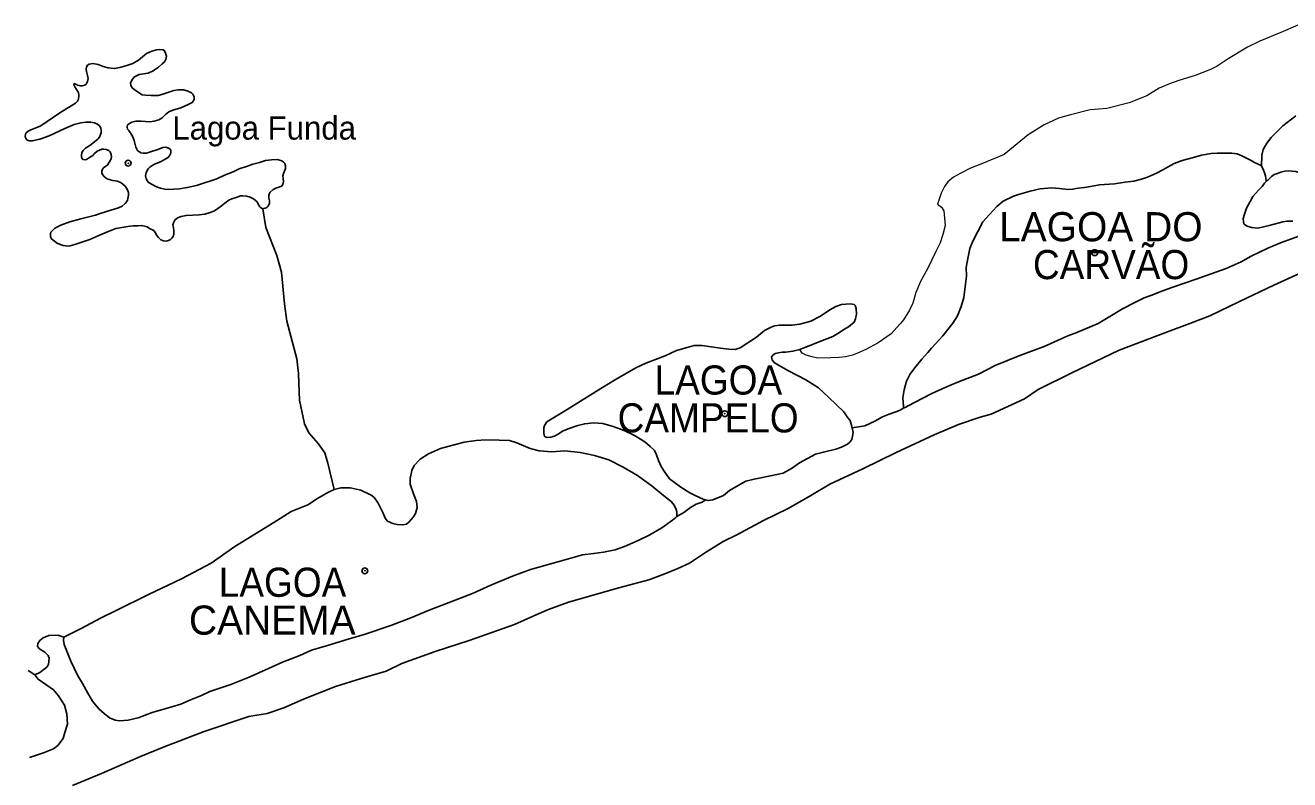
# Model space of a CAD drawing. Extents: x 267.7 to 296, y 7537.7 to 7565.8.
# Drawn here: x 267.927 to 272.267, y 7548.999 to 7551.589 of the extents above; entities that cross this region are included whole.
import ezdxf
from ezdxf.enums import TextEntityAlignment as Align

# ---------------------------------------------------------------- set-up
doc = ezdxf.new("R2010")
doc.units = 0
doc.header["$LTSCALE"] = 0.04
doc.header["$PDMODE"] = 32
doc.header["$PDSIZE"] = 0.02
doc.linetypes.add('SHORT_DASHED', pattern=[2.7, 1.5, -1.2])
for name, color, linetype, lineweight in [('2', 7, 'Continuous', 25), ('21', 7, 'SHORT_DASHED', 13), ('7', 7, 'Continuous', 25)]:
    doc.layers.add(name, color=color, linetype=linetype, lineweight=lineweight)
doc.layers.add('61', color=7, linetype='Continuous')

msp = doc.modelspace()

# ---------------------------------------------------------------- linework, layer by layer
at = {"layer": '2'}
for points in [[(268.1366, 7551.4305), (268.1361, 7551.4383), (268.1366, 7551.4472), (268.1408, 7551.4524), (268.146, 7551.4556), (268.1591, 7551.4582), (268.1768, 7551.455), (268.1946, 7551.4482), (268.2113, 7551.4435), (268.2322, 7551.4409), (268.251, 7551.4446), (268.275, 7551.4514), (268.2965, 7551.4587), (268.3153, 7551.4691), (268.3288, 7551.4806), (268.3435, 7551.4926), (268.3617, 7551.501), (268.3774, 7551.5047), (268.3884, 7551.5062), (268.3999, 7551.5052), (268.4051, 7551.502), (268.4087, 7551.4937), (268.4114, 7551.4832), (268.4093, 7551.4723), (268.4035, 7551.4629), (268.3967, 7551.4576), (268.3837, 7551.4456), (268.3659, 7551.4336), (268.3487, 7551.4253), (268.3179, 7551.4206), (268.3017, 7551.4127), (268.2954, 7551.4049), (268.2886, 7551.3924), (268.2891, 7551.3824), (268.2954, 7551.373), (268.3116, 7551.3605), (268.3278, 7551.3506), (268.3393, 7551.3495), (268.3591, 7551.3485), (268.3826, 7551.348), (268.3952, 7551.3516), (268.437, 7551.3657), (268.4516, 7551.3683), (268.4704, 7551.3683), (268.4829, 7551.3642), (268.497, 7551.3579), (268.5022, 7551.3527), (268.5064, 7551.3433), (268.5064, 7551.3349), (268.5012, 7551.3255), (268.4996, 7551.3245), (268.4855, 7551.3177), (268.461, 7551.3062), (268.4328, 7551.2983), (268.4197, 7551.2926), (268.4082, 7551.2832), (268.3962, 7551.2712), (268.3852, 7551.2644), (268.3691, 7551.2607), (268.3544, 7551.2581), (268.3247, 7551.2597), (268.3059, 7551.2597), (268.2923, 7551.2566), (268.2844, 7551.2524), (268.2776, 7551.2472), (268.2761, 7551.2398), (268.2776, 7551.2331), (268.2818, 7551.2278), (268.2949, 7551.2085), (268.3001, 7551.1939), (268.3059, 7551.1714), (268.3116, 7551.1594), (268.3236, 7551.1521), (268.3325, 7551.15), (268.3435, 7551.1505), (268.3602, 7551.1558), (268.3753, 7551.1605), (268.3905, 7551.1662), (268.3993, 7551.1699), (268.4098, 7551.1709), (268.4187, 7551.1672), (268.4239, 7551.1636), (268.426, 7551.1594), (268.426, 7551.15), (268.4234, 7551.1437), (268.4171, 7551.1354), (268.4072, 7551.1296), (268.391, 7551.1208), (268.3701, 7551.1124), (268.355, 7551.1035), (268.3482, 7551.0967), (268.3419, 7551.0837), (268.3398, 7551.0727), (268.3419, 7551.0617), (268.3487, 7551.0508)], [(268.1366, 7551.4305), (268.1402, 7551.4174), (268.1425, 7551.4064), (268.1405, 7551.3969), (268.1354, 7551.3871), (268.1311, 7551.3844), (268.1225, 7551.3812), (268.1174, 7551.3816), (268.1154, 7551.3816), (268.1115, 7551.3824), (268.1064, 7551.3844), (268.0981, 7551.3883), (268.0958, 7551.3895), (268.0942, 7551.3879), (268.0934, 7551.3852), (268.0954, 7551.3808), (268.0969, 7551.3781), (268.1028, 7551.3691), (268.1095, 7551.3588), (268.1107, 7551.3482), (268.1099, 7551.3353), (268.1064, 7551.3286), (268.0989, 7551.3223), (268.0451, 7551.2889), (267.9803, 7551.2438), (267.961, 7551.2367), (267.9461, 7551.2304), (267.9363, 7551.2257), (267.93, 7551.2206), (267.9277, 7551.2151), (267.9269, 7551.2076), (267.9304, 7551.1982), (267.932, 7551.1962), (267.9363, 7551.1939), (267.9422, 7551.1927), (267.9508, 7551.1923), (267.9764, 7551.1982), (268.009, 7551.2104), (268.0632, 7551.2351), (268.0946, 7551.2489), (268.1174, 7551.2544), (268.1347, 7551.2567), (268.1508, 7551.2571), (268.1645, 7551.2544), (268.1751, 7551.2504), (268.1818, 7551.2442), (268.1857, 7551.2367), (268.1869, 7551.2292), (268.1873, 7551.2206), (268.1849, 7551.2139), (268.1814, 7551.2049), (268.1755, 7551.199), (268.1488, 7551.1762), (268.1339, 7551.1672), (268.1256, 7551.1597), (268.1213, 7551.1526), (268.1193, 7551.1444), (268.1193, 7551.1373), (268.1217, 7551.1314), (268.1256, 7551.1291), (268.1327, 7551.1275), (268.1374, 7551.1287), (268.1476, 7551.135), (268.1582, 7551.1428), (268.1645, 7551.1491), (268.1731, 7551.1573), (268.1814, 7551.1609), (268.19, 7551.164), (268.1967, 7551.1644), (268.2042, 7551.1632), (268.2136, 7551.1593), (268.2179, 7551.1546), (268.2222, 7551.146), (268.2226, 7551.1381), (268.2215, 7551.1318), (268.2183, 7551.124), (268.2128, 7551.1157), (268.2097, 7551.1106), (268.2034, 7551.1059), (268.1955, 7551.0996), (268.1916, 7551.0949), (268.1896, 7551.0878), (268.1893, 7551.0823), (268.1916, 7551.0768), (268.1971, 7551.0698), (268.2054, 7551.0639), (268.2116, 7551.0615), (268.2277, 7551.056), (268.2431, 7551.054), (268.2537, 7551.0501), (268.2603, 7551.0454), (268.2702, 7551.0368), (268.2765, 7551.0265), (268.2808, 7551.0155), (268.2808, 7551.0057)], [(272.1703, 7551.1058), (272.171, 7551.1438), (272.1758, 7551.1629), (272.1885, 7551.1851), (272.2039, 7551.2042), (272.2431, 7551.244), (272.2882, 7551.279)], [(268.4364, 7551.0267), (268.4558, 7551.0278), (268.4829, 7551.032), (268.5143, 7551.0398), (268.5848, 7551.0628), (268.6104, 7551.0748), (268.6401, 7551.0863), (268.6615, 7551.0967), (268.6898, 7551.1061), (268.7075, 7551.1124), (268.7305, 7551.1187), (268.7519, 7551.1249), (268.7718, 7551.127), (268.7921, 7551.1281), (268.8073, 7551.1239), (268.813, 7551.1197), (268.8177, 7551.115), (268.8203, 7551.1067), (268.8203, 7551.0973), (268.8135, 7551.0811), (268.8114, 7551.0727), (268.8125, 7551.0633), (268.8135, 7551.0529), (268.8109, 7551.0429), (268.8067, 7551.0372), (268.801, 7551.0351), (268.7869, 7551.0299), (268.7775, 7551.0257), (268.7665, 7551.0158), (268.7624, 7551.0064), (268.7629, 7550.9959), (268.765, 7550.987), (268.765, 7550.9782), (268.7603, 7550.9688), (268.7571, 7550.9646), (268.754, 7550.963), (268.7425, 7550.9595)], [(270.9429, 7550.2763), (270.9413, 7550.2783), (270.9409, 7550.2811), (270.9397, 7550.3101), (270.9432, 7550.3376), (270.952, 7550.3674), (270.9635, 7550.3909), (270.9791, 7550.4124), (271.0045, 7550.4435), (271.0248, 7550.4661), (271.038, 7550.4813), (271.0766, 7550.5235), (271.1108, 7550.5672), (271.1263, 7550.5915), (271.1391, 7550.6238), (271.1486, 7550.6544), (271.1574, 7550.728), (271.1566, 7550.7583), (271.1618, 7550.7885), (271.1689, 7550.8236), (271.1797, 7550.8482), (271.2135, 7550.9143), (271.2366, 7550.9394), (271.2621, 7550.9672), (271.284, 7550.986), (271.319, 7551.0023), (271.3357, 7551.0082), (271.3767, 7551.0194), (271.4101, 7551.0274), (271.4491, 7551.0309), (271.477, 7551.0293), (271.5057, 7551.0262), (271.5228, 7551.0266), (271.5331, 7551.0289), (271.5709, 7551.0341), (271.6139, 7551.0421), (271.6661, 7551.0449), (271.7027, 7551.0504), (271.7321, 7551.054), (271.7584, 7551.0612), (271.7791, 7551.0679), (271.8101, 7551.0819), (271.834, 7551.0942), (271.8503, 7551.1038), (271.8702, 7551.1153), (271.8985, 7551.1249), (271.9371, 7551.1356), (271.9646, 7551.1432), (271.9976, 7551.1487), (272.0183, 7551.1503), (272.0681, 7551.1503), (272.0864, 7551.1476), (272.1031, 7551.1408), (272.1353, 7551.1257), (272.1445, 7551.1193), (272.1592, 7551.1129), (272.1664, 7551.1089), (272.1703, 7551.1058)], [(272.1703, 7551.1058), (272.176, 7551.0958), (272.1801, 7551.083), (272.1838, 7551.0722), (272.1856, 7551.063), (272.1868, 7551.0562)], [(272.2503, 7551.0881), (272.237, 7551.0848), (272.2214, 7551.0798), (272.2142, 7551.0773), (272.2046, 7551.0702), (272.1974, 7551.0632), (272.1916, 7551.0572), (272.1898, 7551.0564), (272.1868, 7551.0562)], [(272.3077, 7551.079), (272.298, 7551.0843), (272.2884, 7551.0873), (272.2759, 7551.0891), (272.2633, 7551.0896), (272.2503, 7551.0881)], [(268.3487, 7551.0508), (268.3597, 7551.0445), (268.3774, 7551.0351), (268.3915, 7551.0304), (268.4108, 7551.0262), (268.4364, 7551.0267)], [(272.1868, 7551.0562), (272.1861, 7551.0527), (272.1811, 7551.0469), (272.1723, 7551.0365), (272.1596, 7551.0238), (272.1401, 7551.0015), (272.1309, 7550.984), (272.119, 7550.9613), (272.1106, 7550.9378), (272.1079, 7550.9255), (272.1083, 7550.9159), (272.1102, 7550.9079), (272.1154, 7550.9032), (272.121, 7550.9), (272.1361, 7550.8952), (272.158, 7550.8932), (272.1966, 7550.9016), (272.2304, 7550.9115), (272.244, 7550.9143), (272.2583, 7550.9171), (272.2774, 7550.9167)], [(268.2474, 7550.9629), (268.2211, 7550.9551), (268.1834, 7550.9437), (268.168, 7550.937), (268.1174, 7550.9248), (268.0793, 7550.9142), (268.0486, 7550.9032), (268.0353, 7550.8965), (268.0274, 7550.8914), (268.02, 7550.8851), (268.0149, 7550.8789), (268.0129, 7550.8738), (268.0129, 7550.8647), (268.0156, 7550.858), (268.0231, 7550.8514), (268.0361, 7550.8411), (268.0498, 7550.8357), (268.0569, 7550.8333), (268.073, 7550.8309), (268.0804, 7550.8317), (268.0973, 7550.8364), (268.1488, 7550.8541), (268.1794, 7550.8675), (268.2089, 7550.8804), (268.2372, 7550.8914), (268.2792, 7550.8989), (268.2977, 7550.9012), (268.3134, 7550.9009), (268.3248, 7550.9016), (268.3358, 7550.9001), (268.3448, 7550.8977), (268.353, 7550.8922), (268.368, 7550.8844), (268.3727, 7550.8781), (268.3786, 7550.8679), (268.3837, 7550.8608), (268.3884, 7550.8565), (268.3923, 7550.8529), (268.401, 7550.849), (268.41, 7550.8482), (268.4182, 7550.8502), (268.4257, 7550.8537), (268.4304, 7550.8584), (268.4344, 7550.8647), (268.4367, 7550.8726), (268.4363, 7550.8836), (268.4351, 7550.895), (268.4336, 7550.9048), (268.4355, 7550.9115), (268.4402, 7550.9209), (268.4497, 7550.928), (268.4622, 7550.9335), (268.4791, 7550.9366), (268.5235, 7550.939), (268.5432, 7550.9409), (268.562, 7550.9472), (268.5746, 7550.9511), (268.5832, 7550.957), (268.6009, 7550.97), (268.6123, 7550.979), (268.626, 7550.9888), (268.6359, 7550.9936), (268.6512, 7550.9983), (268.6661, 7551.0034), (268.6736, 7551.0038), (268.6877, 7551.003), (268.6987, 7550.9994), (268.7097, 7550.9939), (268.7168, 7550.9884), (268.7223, 7550.9829), (268.7262, 7550.9755), (268.7317, 7550.9664), (268.7356, 7550.9625), (268.7425, 7550.9595)], [(268.2808, 7551.0057), (268.2792, 7550.9943), (268.2772, 7550.9884), (268.2694, 7550.9774), (268.26, 7550.9688), (268.2474, 7550.9629)], [(272.2985, 7550.865), (272.2352, 7550.8431), (272.1922, 7550.824), (272.1353, 7550.7973), (272.1003, 7550.7774), (272.049, 7550.7539), (271.9459, 7550.7177), (271.8663, 7550.6906), (271.8245, 7550.6755), (271.7942, 7550.6632), (271.7679, 7550.6536), (271.7353, 7550.6377), (271.6935, 7550.6162), (271.6557, 7550.5935), (271.6091, 7550.566), (271.5367, 7550.5342), (271.5061, 7550.5231), (271.4241, 7550.4868), (271.3413, 7550.4562), (271.2561, 7550.4212), (271.1984, 7550.3921), (271.1307, 7550.3658), (271.0869, 7550.3471), (271.0384, 7550.3256), (271.0057, 7550.3081), (270.9572, 7550.2827), (270.9472, 7550.2775), (270.944, 7550.2763), (270.9429, 7550.2763)], [(272.3736, 7550.7707), (272.2126, 7550.6967), (272.0925, 7550.6398), (271.9927, 7550.5916), (271.924, 7550.5658), (271.8478, 7550.5369), (271.6816, 7550.4746), (271.5196, 7550.3963), (271.4037, 7550.3394), (271.3565, 7550.3073), (271.2996, 7550.2804), (271.2428, 7550.2547), (271.2041, 7550.244), (271.1301, 7550.2193), (271.0464, 7550.1839), (270.9166, 7550.1227), (270.8018, 7550.0669), (270.6881, 7550.0144), (270.6237, 7549.9757), (270.5454, 7549.9307), (270.4606, 7549.8888), (270.3694, 7549.8406), (270.3222, 7549.817), (270.2654, 7549.7816), (270.2064, 7549.7429), (270.1667, 7549.7247), (270.1227, 7549.7065), (270.0669, 7549.6861), (269.9639, 7549.6582), (269.7912, 7549.6088), (269.7225, 7549.5841), (269.6721, 7549.5616), (269.6056, 7549.5326), (269.4511, 7549.4779), (269.3341, 7549.4393), (269.2193, 7549.3985), (269.1657, 7549.3717), (269.1378, 7549.3642), (269.0798, 7549.347), (268.9919, 7549.3191), (268.8824, 7549.2762), (268.8149, 7549.2462), (268.7569, 7549.2269), (268.6947, 7549.2162), (268.5413, 7549.1647), (268.4039, 7549.1121), (268.3224, 7549.0788), (268.1883, 7549.0209), (268.0885, 7548.9801)], [(269.7182, 7550.1737), (269.712, 7550.1765), (269.7085, 7550.1806), (269.7065, 7550.1917), (269.7065, 7550.2069), (269.7092, 7550.2151), (269.7175, 7550.2275), (269.7865, 7550.2703), (269.9024, 7550.3427), (269.9548, 7550.3745), (270.0224, 7550.4138), (270.0569, 7550.429), (270.1231, 7550.4552), (270.1624, 7550.4731), (270.1983, 7550.4828), (270.2231, 7550.4897), (270.25, 7550.4897), (270.2818, 7550.4855), (270.3128, 7550.4814), (270.3418, 7550.4773), (270.3632, 7550.4759), (270.3804, 7550.4821), (270.437, 7550.5187), (270.4646, 7550.5414), (270.4867, 7550.5531), (270.4991, 7550.5573), (270.5163, 7550.5594), (270.5591, 7550.56), (270.5853, 7550.5635), (270.6025, 7550.5683), (270.6232, 7550.5738), (270.6543, 7550.5897), (270.6736, 7550.6028), (270.6888, 7550.6125), (270.7095, 7550.6235), (270.7281, 7550.6304), (270.7433, 7550.6325), (270.7591, 7550.6332), (270.7716, 7550.6311), (270.7757, 7550.627), (270.7785, 7550.6173), (270.7798, 7550.5973), (270.7764, 7550.5814), (270.7716, 7550.5704), (270.7529, 7550.5545), (270.7371, 7550.5449), (270.7219, 7550.5352), (270.6991, 7550.5214), (270.6577, 7550.5055), (270.6025, 7550.4835), (270.586, 7550.4766)], [(270.586, 7550.4766), (270.5618, 7550.4704), (270.5377, 7550.4669), (270.5253, 7550.4669), (270.5122, 7550.4655), (270.5011, 7550.4621), (270.4929, 7550.4566), (270.488, 7550.4497), (270.4908, 7550.4407), (270.4963, 7550.4331), (270.5046, 7550.4276), (270.5467, 7550.4035), (270.6067, 7550.3724), (270.6495, 7550.3448), (270.6853, 7550.3117), (270.7364, 7550.262), (270.7509, 7550.242), (270.7578, 7550.2331), (270.7619, 7550.2206), (270.7653, 7550.2069)], [(269.7182, 7550.1737), (269.7313, 7550.1751), (269.7437, 7550.1786), (269.7596, 7550.1875), (269.7706, 7550.1958), (269.7899, 7550.2041), (269.8237, 7550.2158), (269.8472, 7550.2213), (269.8775, 7550.2248), (269.9093, 7550.2227), (269.9444, 7550.2117), (269.9831, 7550.1986), (270.0176, 7550.1806), (270.0534, 7550.1593), (270.0714, 7550.1434), (270.0866, 7550.1296), (270.0941, 7550.1151), (270.101, 7550.0958), (270.11, 7550.0751), (270.1197, 7550.0585), (270.1383, 7550.0323), (270.1604, 7550.0158), (270.1776, 7550.004), (270.208, 7549.984), (270.2266, 7549.9751), (270.2535, 7549.9627), (270.2621, 7549.9602)], [(270.2621, 7549.9602), (270.2707, 7549.9578), (270.2866, 7549.9599), (270.3232, 7549.9751), (270.3439, 7549.9923), (270.3818, 7550.0137), (270.3997, 7550.024), (270.4287, 7550.0316), (270.4908, 7550.0434), (270.5287, 7550.0523), (270.557, 7550.0682), (270.5846, 7550.0875), (270.6115, 7550.102), (270.6398, 7550.1165), (270.6667, 7550.1241), (270.7095, 7550.1344), (270.7281, 7550.1406), (270.7495, 7550.151), (270.7571, 7550.1586), (270.764, 7550.1675), (270.7667, 7550.1786), (270.7681, 7550.1917), (270.7653, 7550.2069)], [(268.9866, 7549.9958), (269.0095, 7550.0014), (269.0424, 7550.0014), (269.0785, 7549.9934), (269.1162, 7549.9757), (269.1258, 7549.9669), (269.1386, 7549.9485), (269.1538, 7549.9164), (269.1619, 7549.8979), (269.1707, 7549.8875), (269.1883, 7549.8795), (269.2036, 7549.8755), (269.2228, 7549.8739), (269.2349, 7549.8771), (269.2437, 7549.8835), (269.2597, 7549.902), (269.2669, 7549.9132), (269.2725, 7549.934), (269.2701, 7549.9549), (269.2597, 7549.9814), (269.2485, 7550.0142), (269.2477, 7550.0335), (269.2541, 7550.0608), (269.2621, 7550.0784), (269.2822, 7550.1001), (269.311, 7550.1185), (269.3519, 7550.1361), (269.433, 7550.1578), (269.4747, 7550.1642), (269.5083, 7550.1666), (269.5541, 7550.165), (269.5885, 7550.1634), (269.6142, 7550.1554), (269.6599, 7550.1361), (269.6904, 7550.1281), (269.7345, 7550.1249), (269.7794, 7550.1289), (269.8316, 7550.1225), (269.8813, 7550.1129), (269.9302, 7550.0977), (269.9791, 7550.0728), (270.0281, 7550.0439), (270.0786, 7550.007), (270.105, 7549.9854), (270.1235, 7549.9709), (270.1435, 7549.9549), (270.154, 7549.9421), (270.1612, 7549.9268), (270.1636, 7549.9196), (270.1636, 7549.9036)], [(268.0591, 7549.4889), (268.116, 7549.517), (268.1874, 7549.5555), (268.2363, 7549.5795), (268.3502, 7549.6349), (268.4633, 7549.6894), (268.5644, 7549.7432), (268.6462, 7549.8001), (268.7897, 7549.8883), (268.8395, 7549.9204), (268.8964, 7549.9429), (268.9333, 7549.9677), (268.9678, 7549.987), (268.9866, 7549.9958)], [(268.0591, 7549.4889), (268.0578, 7549.4785), (268.0608, 7549.4642), (268.0834, 7549.4069), (268.1061, 7549.3579), (268.1234, 7549.3293), (268.1415, 7549.2961), (268.1573, 7549.269), (268.1792, 7549.2433), (268.198, 7549.2267), (268.2161, 7549.2124), (268.235, 7549.2041), (268.2508, 7549.2019), (268.2802, 7549.2041), (268.3149, 7549.2117), (268.3624, 7549.2297), (268.4295, 7549.2501), (268.4612, 7549.2591), (268.4913, 7549.2727), (268.532, 7549.2886), (268.5607, 7549.3021), (268.6323, 7549.3262), (268.6949, 7549.3511), (268.7612, 7549.3813), (268.8102, 7549.4031), (268.869, 7549.4258), (268.909, 7549.4439), (268.9648, 7549.4597), (269.0349, 7549.4816), (269.0899, 7549.4981), (269.1819, 7549.5291), (269.2498, 7549.5547), (269.3131, 7549.5818), (269.3726, 7549.6044), (269.4624, 7549.6391), (269.5249, 7549.667), (269.5988, 7549.6987), (269.6606, 7549.7213), (269.6901, 7549.7288), (269.7911, 7549.7582), (269.8401, 7549.7718), (269.8778, 7549.7763), (269.9117, 7549.7809), (269.9517, 7549.7884), (269.9841, 7549.7997), (270.0308, 7549.8201), (270.0708, 7549.8397), (270.1115, 7549.8638), (270.1484, 7549.8902), (270.1605, 7549.8992), (270.1636, 7549.9036)]]:
    msp.add_lwpolyline(points, dxfattribs=at)
for p in [(268.2802, 7551.116), (271.5976, 7550.8088), (270.328, 7550.2559), (269.0925, 7549.7166)]:
    msp.add_point(p, dxfattribs=at)
at = {"layer": '21'}
for points in [[(272.2947, 7551.5894), (272.2363, 7551.5648), (272.1649, 7551.5349), (272.1221, 7551.5142), (272.056, 7551.474), (272.0183, 7551.4493), (271.995, 7551.4376), (271.9431, 7551.4169), (271.886, 7551.4), (271.8549, 7551.3883), (271.8186, 7551.3741), (271.777, 7551.3468), (271.7161, 7551.3235), (271.6395, 7551.304), (271.5825, 7551.2988), (271.515, 7551.282), (271.4735, 7551.2703), (271.4242, 7551.2482), (271.3697, 7551.2132), (271.3321, 7551.1821), (271.2867, 7551.1458), (271.2127, 7551.1146), (271.1712, 7551.0991), (271.1388, 7551.0822), (271.1128, 7551.0679), (271.0934, 7551.0524), (271.0817, 7551.0355), (271.0713, 7551.0134), (271.058, 7550.9748), (271.0718, 7550.9649), (271.0796, 7550.9521), (271.0846, 7550.9019), (271.0767, 7550.8713), (271.0678, 7550.8428)], [(271.0678, 7550.8428), (271.0521, 7550.8132), (271.0392, 7550.7837), (271.0245, 7550.7561), (270.9998, 7550.7098), (270.9841, 7550.6724)], [(270.9841, 7550.6724), (270.9733, 7550.635), (270.9624, 7550.6113), (270.9417, 7550.5778), (270.9304, 7550.565), (270.9191, 7550.5522), (270.8994, 7550.5296), (270.8541, 7550.499), (270.8117, 7550.4764), (270.7832, 7550.4636), (270.7664, 7550.4567), (270.7428, 7550.4517), (270.7201, 7550.4488), (270.6915, 7550.4478), (270.6472, 7550.4468), (270.6275, 7550.4517), (270.6068, 7550.4567), (270.594, 7550.4636), (270.586, 7550.4766)]]:
    msp.add_lwpolyline(points, dxfattribs=at)
at = {"layer": '7'}
msp.add_line((267.9592, 7549.359), (267.9373, 7549.3747), dxfattribs=at)
for points in [[(268.9866, 7549.9958), (268.9649, 7550.086), (268.9546, 7550.1216), (268.9321, 7550.1536), (268.9005, 7550.1902), (268.8857, 7550.2209), (268.8682, 7550.3028), (268.8664, 7550.3611), (268.8644, 7550.3939), (268.8593, 7550.4444), (268.8249, 7550.5739), (268.8161, 7550.633), (268.8063, 7550.7422), (268.7904, 7550.7994), (268.753, 7550.8948), (268.7425, 7550.9595)], [(270.7653, 7550.2069), (270.8084, 7550.2144), (270.8435, 7550.2301), (270.8699, 7550.2453), (270.8917, 7550.2545), (270.9156, 7550.2621), (270.9303, 7550.2677), (270.9429, 7550.2763)], [(270.1636, 7549.9036), (270.1875, 7549.9168), (270.2103, 7549.9336), (270.2301, 7549.9453), (270.2499, 7549.9524), (270.2621, 7549.9602)], [(267.9592, 7549.359), (267.9765, 7549.3675), (268.0011, 7549.386), (268.0067, 7549.3952), (268.0087, 7549.4167), (268.0057, 7549.4259), (267.9942, 7549.4377), (267.9755, 7549.4486), (267.9683, 7549.4568), (267.9703, 7549.4671), (267.9765, 7549.4773), (267.9878, 7549.4866), (268.0073, 7549.4948), (268.0381, 7549.4958), (268.0591, 7549.4889)], [(267.9418, 7549.0757), (267.9516, 7549.079), (267.9898, 7549.0914), (268.0237, 7549.1058), (268.0384, 7549.1168), (268.0566, 7549.1407), (268.0628, 7549.1614), (268.0713, 7549.1897), (268.07, 7549.2257), (268.0616, 7549.2558), (268.0412, 7549.2876), (268.0242, 7549.3078), (267.971, 7549.3443), (267.9592, 7549.359)]]:
    msp.add_lwpolyline(points, dxfattribs=at)

# ---------------------------------------------------------------- texts
at = {"layer": '61'}
msp.add_text('Lagoa Funda', height=0.08, dxfattribs=at).set_placement((268.4315, 7551.197))
for s, p in [('LAGOA DO', (271.6187, 7550.8479)), ('CANEMA', (268.7747, 7549.4974))]:
    msp.add_text(s, height=0.1, dxfattribs=at).set_placement(p, align=Align.CENTER)
at = {"layer": '61', "width": 0.95}
for s, p in [('  CARVÃO', (271.6188, 7550.7179)), ('  LAGOA', (270.2707, 7550.3217)), ('CAMPELO', (270.2708, 7550.1917)), ('  LAGOA', (268.7747, 7549.6274))]:
    msp.add_text(s, height=0.1, dxfattribs=at).set_placement(p, align=Align.CENTER)

doc.saveas('drawing.dxf')
